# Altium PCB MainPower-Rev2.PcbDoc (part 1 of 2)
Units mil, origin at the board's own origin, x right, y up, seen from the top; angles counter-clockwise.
Board outline 7780 x 7780 mil, 4 copper layers (Top Layer, Internal Plane 1, Internal Plane 2, Bottom Layer); 128 components, 89 nets, 523 pads, 30 vias.
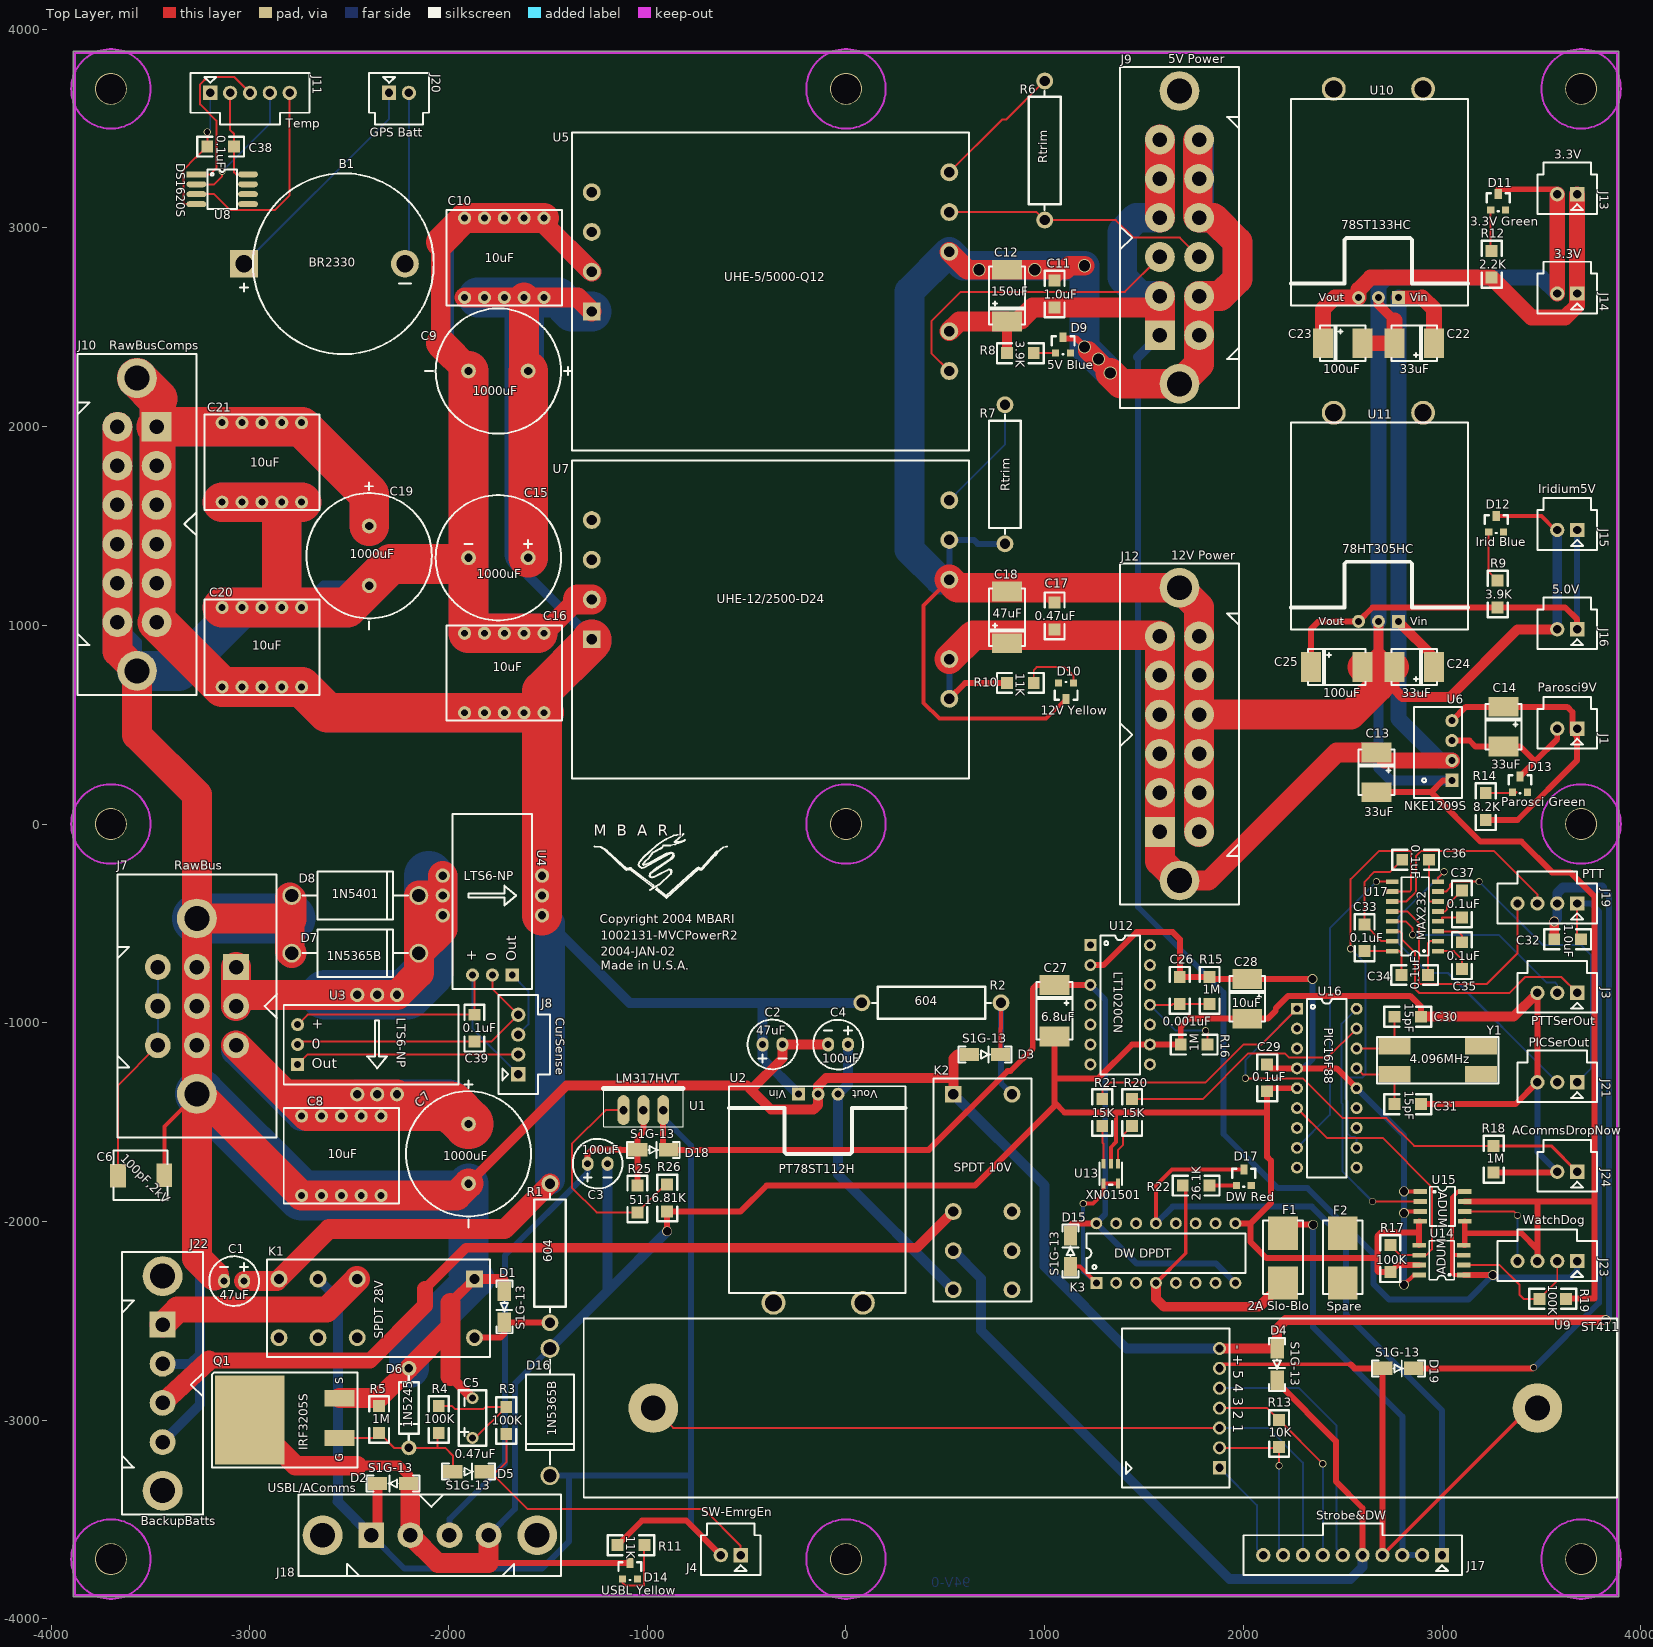
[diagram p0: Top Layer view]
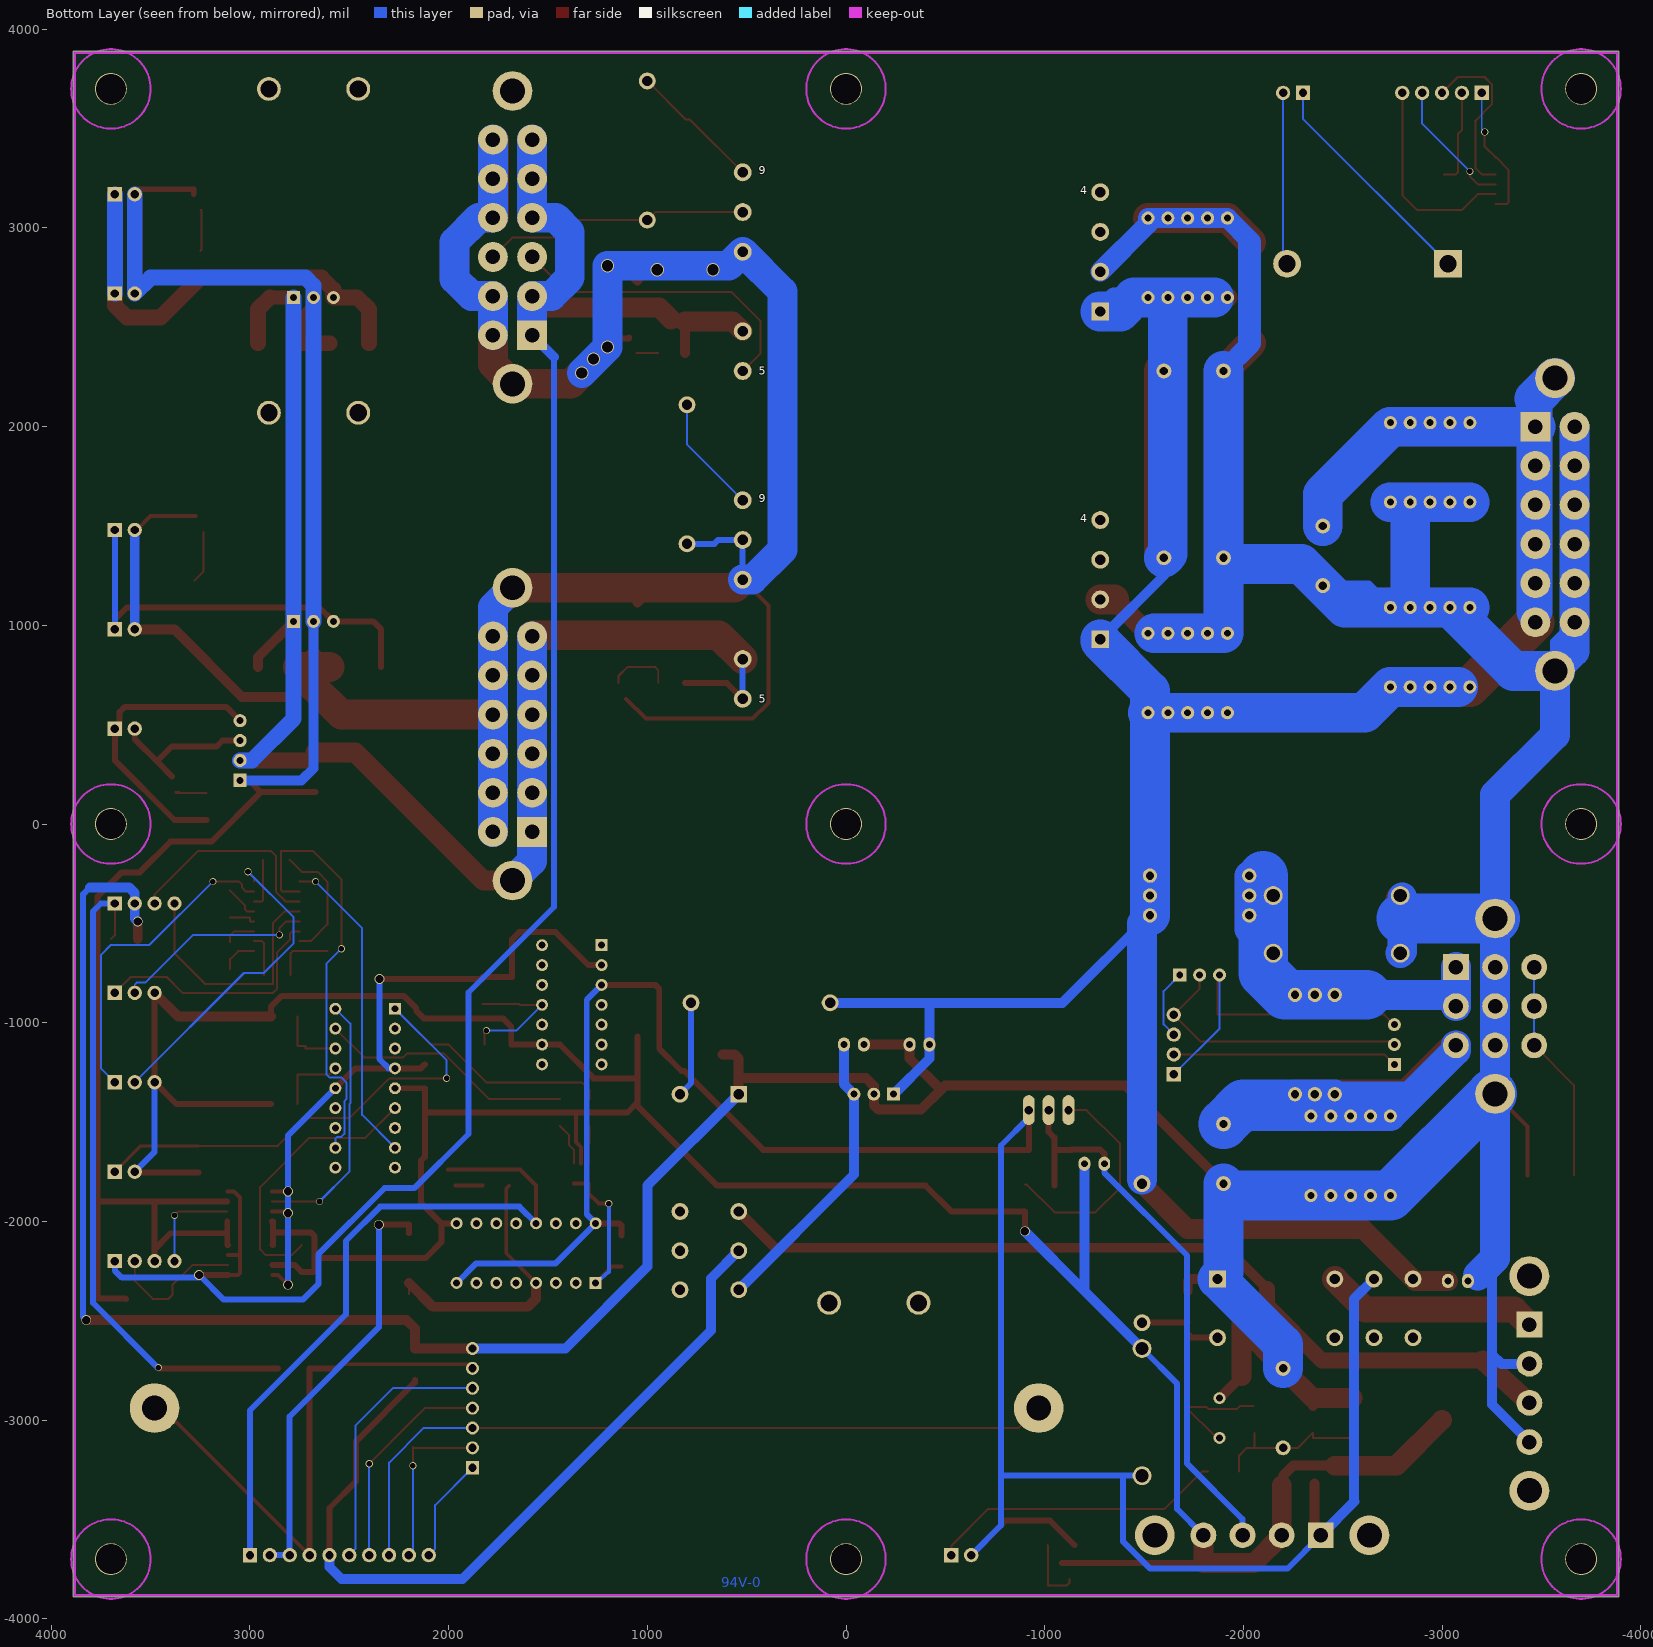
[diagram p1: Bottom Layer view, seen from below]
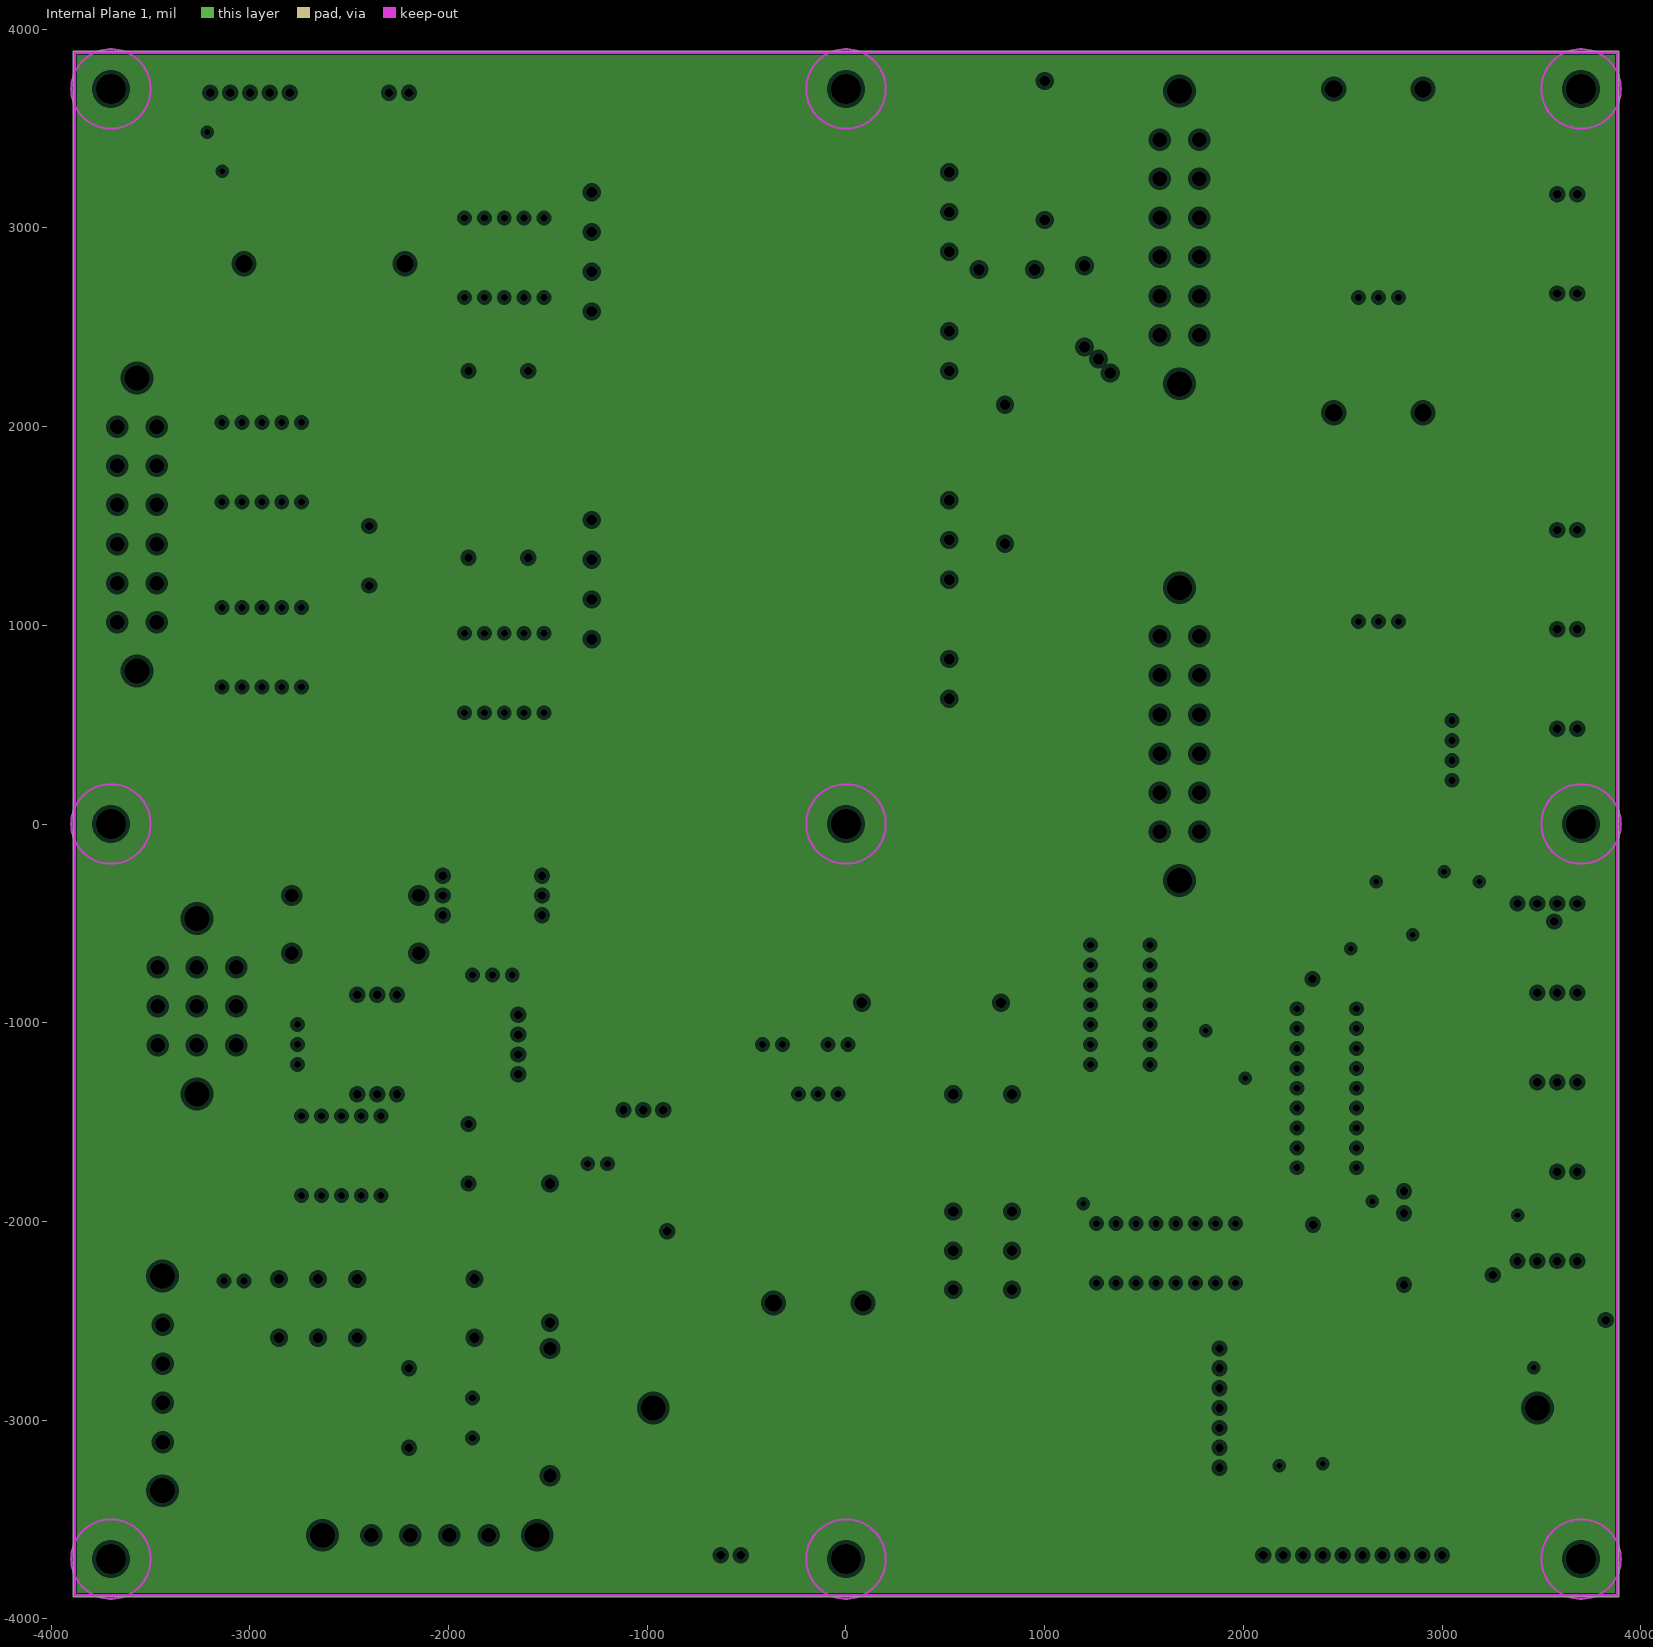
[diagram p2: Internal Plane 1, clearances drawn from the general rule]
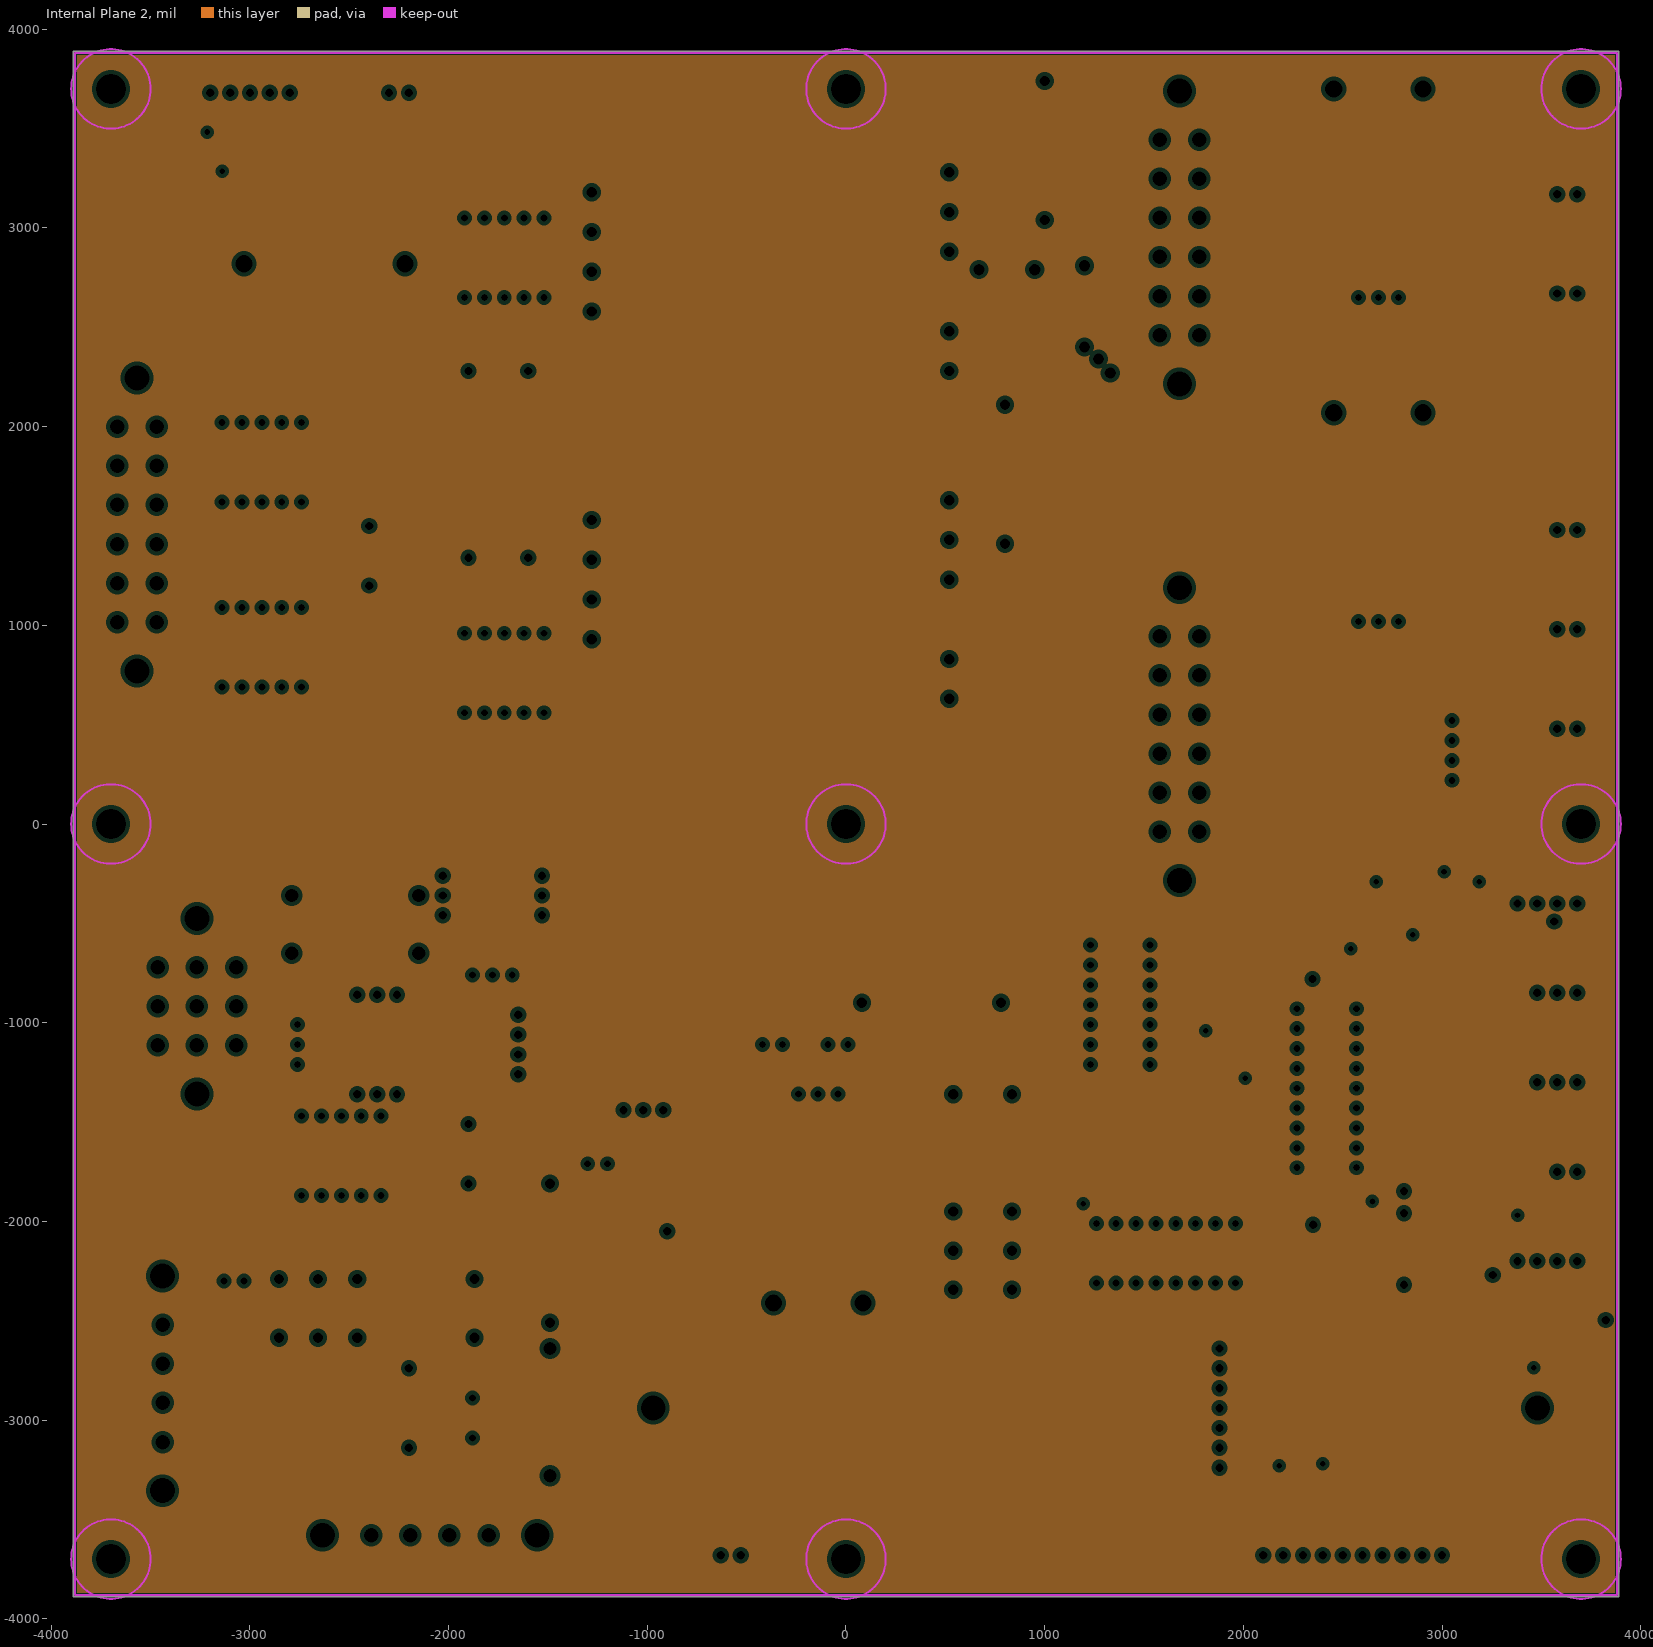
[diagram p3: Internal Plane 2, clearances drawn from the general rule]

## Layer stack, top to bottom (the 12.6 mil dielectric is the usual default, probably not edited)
Top Layer: signal copper 1.4
Dielectric: dielectric 12.6, FR-4, Dk 4.8
Internal Plane 1: plane copper 1.4
Dielectric: dielectric 12.6, FR-4, Dk 4.8
Internal Plane 2: plane copper 1.4
Dielectric: dielectric 12.6, FR-4, Dk 4.8
Bottom Layer: signal copper 1.4

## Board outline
-3890,3890 3890,3890 3890,-3890 -3890,-3890

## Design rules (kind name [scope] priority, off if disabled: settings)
Clearance Clearance_u13 [InPadClass('fineSMT')] p1: gap=10
Clearance powers [(InNetClass('BackupBattPower') OR InNetClass('RawPower') OR InNetClass('RegVoltage'))] p2: gap=20
Clearance [All] p3: gap=10
ComponentClearance [All] p1 off: gap=10 collisioncheckmode=0
FanoutControl Fanout_Small [(CompPinCount < 5)] p1: bgadir=Out bgaviamode=Centered fanoutstyle=Auto fanoutdirection=OutThenIn viagrid=1 // Fanout_Small (Default Rule)
FanoutControl Fanout_Default [All] p2: bgadir=Out bgaviamode=Centered fanoutstyle=Auto fanoutdirection=Alternating viagrid=1 // Fanout_Default (Default Rule)
FanoutControl Fanout_BGA [IsBGA] p4: bgadir=Out bgaviamode=Centered fanoutstyle=Auto fanoutdirection=Alternating viagrid=1 // Fanout_BGA (Default Rule)
FanoutControl Fanout_LCC [IsLCC] p5: bgadir=Out bgaviamode=Centered fanoutstyle=Auto fanoutdirection=Alternating viagrid=1 // Fanout_LCC (Default Rule)
HoleSize [All] p1: absolutevalues=TRUE maxlimit=250 minlimit=1 maxpercent=80.000 minpercent=20.000
PlaneClearance [All] p1: clearance=20
PlaneConnect [All] p1: planeconnectstyle=Relief reliefexpansion=20 reliefentries=4 reliefconductorwidth=10 reliefairgap=10
PolygonConnect [All] p1: connectstyle=Relief reliefconductorwidth=30 reliefentries=4 polygonreliefangle="90 Angle"
RoutingCorners [All] p1: cornerstyle=Round minsetback=50 maxsetback=1000
RoutingLayers [All] p1: top layer=Horizontal bottom layer=Vertical
RoutingPriority raw_powers [InNetClass('RawPower')] p1: routingpriority=90
RoutingPriority regpow [InNetClass('RegVoltage')] p2: routingpriority=70
RoutingPriority battpow [InNetClass('BackupBattPower')] p3: routingpriority=80
RoutingPriority [All] p4: routingpriority=0
RoutingVias RoutingVias_power [(InNetClass('BackupBattPower') OR InNetClass('RawPower') OR InNetClass('RegVoltage'))] p1: holewidth=42 width=50 viastyle="Through Hole" minholewidth=35 minwidth=43 maxholewidth=86 maxwidth=100
RoutingVias [All] p2: holewidth=28 width=36 viastyle="Through Hole" minholewidth=28 minwidth=35 maxholewidth=86 maxwidth=100
SolderMaskExpansion [All] p1: expansion=4
TestPointUsage [All] p1: valid=0 allowmultiple=FALSE
Testpoint [All] p1: side=15 testpointundercomponent=TRUE minsize=40 maxsize=100 preferedsize=60 minholesize=0 maxholesize=40 preferedholesize=32 testpointgrid=1 style=1023 order=-539222988
Width raw_power [InNetClass('RawPower')] p1: maxlimit=500 minlimit=10 preferedwidth=10 toplayer_minwidth=20 toplayer_prefwidth=250 bottomlayer_minwidth=20 bottomlayer_prefwidth=250 minimp=50.000000 maximp=50.000000 favimp=50.000000
Width backup_batt_pow [InNetClass('BackupBattPower')] p2: maxlimit=500 minlimit=10 preferedwidth=10 toplayer_minwidth=20 toplayer_prefwidth=50 bottomlayer_minwidth=20 bottomlayer_prefwidth=50 minimp=50.000000 maximp=50.000000 favimp=50.000000
Width reg_pow [InNetClass('RegVoltage')] p3: maxlimit=250 minlimit=10 preferedwidth=10 toplayer_minwidth=20 toplayer_prefwidth=80 bottomlayer_minwidth=20 bottomlayer_prefwidth=150 minimp=50.000000 maximp=50.000000 favimp=50.000000
Width [All] p4: maxlimit=500 minlimit=8 preferedwidth=12 toplayer_prefwidth=10 bottomlayer_prefwidth=10 minimp=50.000000 maximp=50.000000 favimp=50.000000
7 further rules are at their usual default settings.

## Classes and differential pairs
component class Watchdog-Rev2: C26 C27 C28 C29 C30 C31 C33 C34 C35 C36 C37 D15 D17 F1 F2 J3 J21 J25 J26 K3 R15 R16 R17 R18 R19 R20 R21 R22 R23 R24 U12 U13 U14 U15 U16 U17 Y1
component class "Parosci Iso": C13 C14 U6
component class MainPower-Rev2: B1 C19 C20 C21 C32 C38 D9 D10 D11 D12 D13 D14 D19 J1 J7 J8 J9 J10 J11 J12 J13 J14 J15 J16 J17 J18 J19 J20 J22 J23 J24 R8 R9 R10 R11 R12 R13 R14 U8 U9
component class Iridium: C24 C25 U11
component class Input-Caps-Diodes-CurrentSensing: C6 C7 C8 C39 D7 D8 U3 U4
component class ISO12V-30W-MVC-Rev2: C15 C16 C17 C18 R7 U7
component class ISO5V-25W-MVC-Rev2: C9 C10 C11 C12 R6 U5
component class GPS: C22 C23 U10
component class BattBacked-Rev2: C1 C2 C3 C4 C5 D1 D2 D3 D4 D5 D6 D16 D18 J4 K1 K2 Q1 R1 R2 R3 R4 R5 R25 R26 U1 U2
net class BackupBattPower: 12VSWBU BACKUP10+ BACKUP28+ DW28V DW+ DW- DWGND SW10VDC V+USBL
net class RegVoltage: DW5V IRID5V+ MVC3.3V+ MVC5V+ MVC12V+ MVCGND PARO9V+ PARO9VGND SW10VDC V+USBL
net class RawPower: ELEC+ LOCO+ RAWBUS+ RAWBUS-
pad class fineSMT: U13-1 U13-2 U13-3 U13-4 U13-5 U14-1 U14-2 U14-3 U14-4 U14-5 U14-6 U14-7 U14-8 U15-1 U15-2 U15-3 U15-4 U15-5 U15-6 U15-7 U15-8 U16-4 U16-5

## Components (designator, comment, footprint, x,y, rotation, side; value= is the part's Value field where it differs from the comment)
B1 "BR2330" BR2330-BAT -2530,2820 r180 top
C1 "47uF" RAD0.1L_0.25D -3030,-2300 r180 top
C2 "47uF" RAD0.1L_0.25D -420,-1110 r0 top
C3 "100uF" RAD0.1L_0.25D -1300,-1710 r0 top
C4 "100uF" RAD0.1L_0.25D 10,-1110 r180 top
C5 "0.47uF" RAD0.2_POL -1880,-3090 r90 top
C6 "100pF,2kV" ECK -3670,-1750 r0 top
C7 "1000uF" RAD0.3L_0.63D -1900,-1510 r270 top
C8 "10uF" CAPSTICK-CS4-5 -2740,-1470 r0 top
C9 "1000uF" RAD0.3L_0.63D -1600,2280 r180 top
C10 "10uF" CAPSTICK-CS4-5 -1520,2650 r180 top
C11 "1.0uF" 1206 1050,2600 r90 top
C12 "150uF" 7343pol 810,2530 r90 top
C13 "33uF" 6032pol 2670,360 r270 top
C14 "33uF" 6032pol 3310,590 r270 top
C15 "1000uF" RAD0.3L_0.63D -1600,1340 r180 top
C16 "10uF" CAPSTICK-CS4-5 -1520,560 r180 top
C17 "0.47uF" 1206 1050,980 r90 top
C18 "47uF" 7343pol 810,910 r90 top
C19 "1000uF" RAD0.3L_0.63D -2400,1500 r270 top
C20 "10uF" CAPSTICK-CS4-5 -2740,690 r180 top
C21 "10uF" CAPSTICK-CS4-5 -3140,2020 r0 top
C22 "33uF" 6032pol 2960,2420 r180 top
C23 "100uF" 6032pol 2400,2420 r0 top
C24 "33uF" 6032pol 2960,790 r180 top
C25 "100uF" 7343pol 2340,790 r0 top
C26 "0.001uF" 1206 1680,-770 r270 top
C27 "6.8uF" 7343pol 1050,-810 r270 top
C28 "10uF" 6032pol 2020,-780 r270 top
C29 "0.1uF" 1206 2120,-1210 r270 top
C30 "15pF" 1206 2760,-970 r0 top
C31 "15pF" 1206 2760,-1410 r0 top
C32 "1.0uF" 1206 3700,-580 r180 top
C33 "0.1uF" 1206 2610,-640 r90 top
C34 "0.1uF" 1206 2930,-760 r180 top
C35 "0.1uF" 1206 3100,-730 r90 top
C36 "0.1uF" 1206 2800,-180 r0 top
C37 "0.1uF" 1206 3100,-470 r90 top
C38 "0.1uF" 1206 -3080,3410 r180 top
C39 "0.1uF" 1206 -1870,-960 r270 top
D1 "S1G-13" SMA -1720,-2430 r270 top
D2 "S1G-13" SMA -2280,-3320 r180 top
D3 "S1G-13" SMA 700,-1160 r0 top
D4 "S1G-13" SMA 2170,-2720 r270 top
D5 "S1G-13" SMA -1900,-3260 r0 top
D6 "1N5245" DIODE0.4 -2200,-2740 r270 top
D7 "1N5365B" DO-201AD -2790,-650 r0 top
D8 "1N5401" DO-201AD -2790,-360 r0 top
D9 "5V Blue" SOT-23 1130,2370 r0 top
D10 "12V Yellow" SOT-23 1070,710 r180 top
D11 "3.3V Green" SOT-23 3320,3090 r0 top
D12 "Irid Blue" SOT-23 3310,1470 r0 top
D13 "Parosci Green" SOT-23 3430,160 r0 top
D14 "USBL Yellow" SOT-23 -1050,-3800 r0 top
D15 "S1G-13" SMA 1130,-2150 r90 top
D16 "1N5365B" DO-201AD -1490,-2640 r270 top
D17 "DW Red" SOT-23 2040,-1820 r0 top
D18 "S1G-13" SMA -970,-1640 r0 top
D19 "S1G-13" SMA 2780,-2740 r0 top
F1 "2A Slo-Blo" SMF-OMNIBLOK 2200,-2310 r90 top
F2 "Spare 2A Slo-Blo" SMF-OMNIBLOK 2500,-2310 r90 top
J1 "Parosci9V" CGRID2 3680,480 r0 top
J3 "PTTSerOut" CGRID3 3680,-850 r0 top
J4 "SW-EmrgEn" CGRID2 -530,-3680 r0 top
J7 "RawBus" PLC09 -3070,-720 r270 top
J8 "CurSense" CGRID4 -1650,-1260 r270 top
J9 "5V Power" PLB12 1580,2460 r90 top
J10 "RawBusComps" PLB12 -3470,2000 r270 top
J11 "Temp" CGRID5 -3200,3680 r180 top
J12 "12V Power" PLB12 1580,-40 r90 top
J13 "3.3V" CGRID2 3680,3170 r0 top
J14 "3.3V" CGRID2 3680,2670 r0 top
J15 "Iridium5V" CGRID2 3680,1480 r0 top
J16 "5.0V" CGRID2 3680,980 r0 top
J17 "Strobe&DW" CGRID10 3000,-3680 r0 top
J18 "USBL/AComms" PLA04 -2390,-3580 r0 top
J19 "PTT" CGRID4 3680,-400 r0 top
J20 "GPS Batt" CGRID2 -2300,3680 r180 top
J21 "PICSerOut" CGRID3 3680,-1300 r0 top
J22 "BackupBatts" PLA04 -3440,-2520 r270 top
J23 "WatchDog" CGRID4 3680,-2200 r0 top
J24 "ACommsDropNow" CGRID2 3680,-1750 r0 top
K1 "SPDT 28V" NAIS-LZ -1870,-2290 r180 top
K2 "SPDT 10V" NAIS-LZ 540,-1360 r270 top
K3 "DW DPDT" DIP16 1260,-2310 r90 top
Q1 "IRF3205S" D2PAK -2550,-3090 r90 top
R1 "604" AXIAL0.7 -1490,-2510 r90 top
R2 "604" AXIAL0.7 780,-900 r180 top
R3 "100K" 1206 -1710,-3070 r90 top
R4 "100K" 1206 -2050,-2930 r270 top
R5 "1M" 1206 -2350,-2930 r270 top
R6 "Rtrim" AXIAL0.7 1000,3740 r270 top
R7 "Rtrim" AXIAL0.7 800,2110 r270 top
R8 "3.9K" 1206 810,2370 r0 top
R9 "3.9K" 1206 3280,1090 r90 top
R10 "11K" 1206 810,710 r0 top
R11 "11K" 1206 -1150,-3630 r0 top
R12 "2.2K" 1206 3250,2750 r90 top
R13 "10K" 1206 2180,-3000 r270 top
R14 "8.2K" 1206 3220,20 r90 top
R15 "1M" 1206 1830,-770 r270 top
R16 "1M" 1206 1820,-1110 r180 top
R17 "100K" 1206 2740,-2120 r270 top
R18 "1M" 1206 3260,-1620 r270 top
R19 "100K" 1206 3490,-2390 r0 top
R20 "15K" 1206 1440,-1520 r90 top
R21 "15K" 1206 1290,-1520 r90 top
R22 "26.1K" 1206 1830,-1820 r180 top
R25 "511" 1206 -1050,-1820 r270 top
R26 "6.81K" 1206 -900,-1950 r90 top
U1 "LM317HVT" TO-220 -1120,-1440 r0 top
U2 "PT78ST112H" PT78ST-HORIZ -140,-1360 r180 top
U3 "LTS6-NP" LTS6-NP -2830,-910 r0 top
U4 "LTS6-NP" LTS6-NP -1980,-830 r90 top
U5 "UHE-5/5000-Q12" DATEL-UHE -1280,2580 r0 top locked
U6 "NKE1209S" NKEDCDC 3050,220 r180 top
U7 "UHE-12/2500-D24" DATEL-UHE -1280,930 r0 top locked
U8 "DS1620S" SOIC-8 -3270,3270 r0 top
U9 "ST411" ST411 3880,-2940 r270 top locked
U10 "78ST133HC" PT78ST-HORIZ 2680,2650 r0 top
U11 "78HT305HC" PT78ST-HORIZ 2680,1020 r0 top
U12 "LT1020CN" DIP14 1230,-610 r0 top
U13 "XN01501" SC-74A 1370,-1810 r0 top
U14 "ADUM1100AR" SO-G8/D5 3110,-2270 r90 top
U15 "ADUM1100AR" SO-G8/D5 2890,-1850 r270 top
U16 "PIC16F88" DIP18 2270,-930 r0 top
U17 "MAX232" SOIC-16-0.15W 2980,-640 r90 top
Y1 "4.096MHz" MA-506 2760,-1260 r0 top

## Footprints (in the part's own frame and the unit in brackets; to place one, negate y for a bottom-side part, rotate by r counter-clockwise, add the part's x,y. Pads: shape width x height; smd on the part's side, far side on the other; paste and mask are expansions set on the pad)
1206 [mil]
  rect 60x60 smd: 1(0,0) 2(135,0)
  silkscreen extent -50,-50 185,50
6032pol [mil]
  rect 100x150 smd: 1(0,0) 2(200,0)
  silkscreen extent -15,-90 215,90
7343pol [mil]
  rect 100x150 smd: 1(0,0) 2(260,0)
  silkscreen extent -15,-90 275,90
AXIAL0.7 [mil]
  round 85 hole 52: 1(0,0) 2(700,0)
  silkscreen extent 50,-80 650,80
BR2330-BAT [mil] "BR2330 lithium battery horiz mounted"
  rect 140x140 hole 86: 1(500,0)
  round 140 hole 86: 2(-310,0)
  silkscreen extent -455,-455 520,455
CAPSTICK-CS4-5 [mil]
  round 66 hole 35: 1(0,0) 1(100,0) 1(200,0) 1(300,0) 1(400,0) 2(0,-400) 2(100,-400) 2(200,-400) 2(300,-400) 2(400,-400)
  silkscreen extent -90,-440 490,40
CGRID2 [mil]
  rect 72x72 hole 42: 1(0,0)
  round 72 hole 42: 2(-100,0)
  silkscreen extent -200,-100 100,160
CGRID3 [mil]
  rect 72x72 hole 42: 1(0,0)
  round 72 hole 42: 2(-100,0) 3(-200,0)
  silkscreen extent -300,-100 100,160
CGRID4 [mil]
  rect 72x72 hole 42: 1(0,0)
  round 72 hole 42: 2(-100,0) 3(-200,0) 4(-300,0)
  silkscreen extent -400,-100 100,160
CGRID5 [mil]
  rect 72x72 hole 42: 1(0,0)
  round 72 hole 42: 2(-100,0) 3(-200,0) 4(-300,0) 5(-400,0)
  silkscreen extent -500,-100 100,160
CGRID10 [mil] "10 pin Molex CGRID-SL straight"
  rect 72x72 hole 42: 1(0,0)
  round 72 hole 42: 2(-100,0) 3(-200,0) 4(-300,0) 5(-400,0) 6(-500,0) 7(-600,0) 8(-700,0) 9(-800,0) 10(-900,0)
  silkscreen extent -1000,-100 100,160
D2PAK [mil] "IRF D2Pak SMD-220"
  rect 82x150 smd: 1(0,0) 3(200,0)
  rect 450x350 smd: 2(90,450)
  silkscreen extent -150,-90 330,640
DATEL-UHE [mil] "Datel UHE 1.6x2.0 DC/DC Converter"
  rect 90x90 hole 52: 1(0,0)
  round 90 hole 52: 2(0,200) 3(0,400) 4(0,600) 5(1800,-300) 6(1800,-100) 7(1800,300) 8(1800,500) 9(1800,700)
  silkscreen extent -100,-700 1900,900
DIODE0.4 [mil]
  round 75 hole 42: 1(0,0) 2(400,0)
  silkscreen extent 40,-50 360,50
DIP14 [mil]
  rect 60x60 hole 35: 1(0,0)
  round 60 hole 35: 2(0,-100) 3(0,-200) 4(0,-300) 5(0,-400) 6(0,-500) 7(0,-600) 8(300,-600) 9(300,-500) 10(300,-400) 11(300,-300) 12(300,-200) 13(300,-100) 14(300,0)
  silkscreen extent 50,-650 250,50
DIP16 [mil]
  rect 60x60 hole 35: 1(0,0)
  round 60 hole 35: 2(0,-100) 3(0,-200) 4(0,-300) 5(0,-400) 6(0,-500) 7(0,-600) 8(0,-700) 9(300,-700) 10(300,-600) 11(300,-500) 12(300,-400) 13(300,-300) 14(300,-200) 15(300,-100) 16(300,0)
  silkscreen extent 50,-750 250,50
DIP18 [mil]
  rect 60x60 hole 35: 1(0,0)
  round 60 hole 35: 2(0,-100) 3(0,-200) 4(0,-300) 5(0,-400) 6(0,-500) 7(0,-600) 8(0,-700) 9(0,-800) 10(300,-800) 11(300,-700) 12(300,-600) 13(300,-500) 14(300,-400) 15(300,-300) 16(300,-200) 17(300,-100) 18(300,0)
  silkscreen extent 50,-850 250,50
DO-201AD [mil]
  round 95 hole 67: 1(0,0) 2(640,0)
  silkscreen extent 55,-120 585,120
ECK [mm]
  rect 2x3 smd: 1(0.15,-0.5) 2(6.075,-0.475)
  silkscreen extent -0.4,-3.6 6.5,2.7
LTS6-NP [mil]
  round 72 hole 42: 1(370,-450) 2(470,-450) 3(570,-450) 4(570,50) 5(470,50) 6(370,50)
  rect 66x66 hole 35: a(70,-300)
  round 66 hole 35: b(70,-200) c(70,-100)
  silkscreen extent 0,-400 880,0
MA-506 [mm] "Epson Quartz Crystal"
  rect 4.1x2.1 smd: 1(0,0) 2(11.1,0) 3(11.1,3.6) 4(0,3.6)
  silkscreen extent -2.2,-1.2 13.3,4.8
NAIS-LZ [mil] "NAIS LZ Relay"
  rect 85x85 hole 52: 1(0,0)
  round 85 hole 52: 2(590.55,0) 3(787.4,0) 4(984.25,0) 5(984.25,295.28) 6(787.4,295.28) 7(590.55,295.28) 8(0,295.28)
  silkscreen extent -79,-98 1043,394
NKEDCDC [mil]
  rect 66x66 hole 35: 1(0,0)
  round 66 hole 35: 2(0,-100) 3(0,-200) 4(0,-300)
  silkscreen extent -50,-370 190,90
PLA04 [mil] "Positronic 1x4 pin"
  round 200 hole 125: 0(-244.5,0) 0(835.5,0)
  rect 130x130 hole 73: 1(0,0)
  round 130 hole 73: 2(197,0) 3(394,0) 4(591,0)
  silkscreen extent -366,-204 956,204
PLB12 [mil] "Positronic 2x6 pin"
  round 200 hole 125: 0(-244.5,-98.5) 0(1229.5,-98.5)
  rect 150x150 hole 73: 1(0,0)
  round 150 hole 73: 2(197,0) 3(394,0) 4(591,0) 5(788,0) 6(985,0) 7(0,-197) 8(197,-197) 9(394,-197) 10(591,-197) 11(788,-197) 12(985,-197)
  silkscreen extent -366,-398 1350,202
PLC09 [mil] "Positronic 3x3 pins"
  round 200 hole 125: 0(-244.5,-197) 0(638.5,-197)
  rect 130x130 hole 73: 1(0,0)
  round 130 hole 73: 2(197,0) 3(394,0) 4(0,-197) 5(197,-197) 6(394,-197) 7(0,-394) 8(197,-394) 9(394,-394)
  silkscreen extent -465,-598 859,205
PT78ST-HORIZ [mil]
  round 120 hole 86: 0(-225,1050) 0(225,1050)
  rect 65x65 hole 35: 1(100,0)
  round 65 hole 35: 2(0,0) 3(-100,0)
  silkscreen extent -440,-40 450,1000
RAD0.1L_0.25D [mil]
  oval 60x72 hole 35: 1(0,0) 2(100,0)
  silkscreen extent -75,-125 175,125
RAD0.2_POL [mil] "Polarized Cap"
  round 60 hole 35: 1(0,0) 2(200,0)
  silkscreen extent -40,-70 240,70
RAD0.3L_0.63D [mil]
  round 75 hole 42: 1(0,0) 2(300,0)
  silkscreen extent -220,-315 520,315
SC-74A [mil] "Mini5 - G1 Panasonic"
  rect 20x50 smd: 1(0,0) 2(-75,0) 3(-75,100) 4(-37,100) 5(0,100)
  silkscreen extent -95,-8 19,106
SMA [mm] "SMA Diode"
  rect 2.5x1.7 smd: 1(-2,0) 2(2,0)
  silkscreen extent -3.38,-1.02 3.38,1.02
SMF-OMNIBLOK [mil] "SMD Nano Fuse Holder"
  rect 167x150 smd: 1(0,0) 2(250,0)
  silkscreen extent -55,-100 315,100
SO-G8/D5 [mm]
  rect 0.6x1.7 smd: 1(0,0) 2(1.27,0) 3(2.54,0) 4(3.81,0) 5(3.81,5.7) 6(2.54,5.7) 7(1.27,5.7) 8(0,5.7)
  silkscreen extent -0.59,1.25 4.41,4.45
SOIC-8 [mil]
  rect 100x30 smd: 1(0,0)
  oval 100x30 smd: 2(0,-50) 3(0,-100) 4(0,-150) 5(260,-150) 6(260,-100) 7(260,-50) 8(260,0)
  silkscreen extent 55,-175 205,25
SOIC-16-0.15W [mm] "SOIC-16 0.15\"Wide 1.27mm Pitch"
  rect 0.6x1.55 smd: 1(0,0) 2(1.27,0) 3(2.54,0) 4(3.81,0) 5(5.08,0) 6(6.35,0) 7(7.62,0) 8(8.89,0) 9(8.89,5.85) 10(7.62,5.85) 11(6.35,5.85) 12(5.08,5.85) 13(3.81,5.85) 14(2.54,5.85) 15(1.27,5.85) 16(0,5.85)
  silkscreen extent -0.55,1.18 9.44,4.67
SOT-23 [mil]
  rect 36x36 smd: 1(0,0) 2(-75,0)
  rect 36x50 smd: 3(-37,80)
  silkscreen extent -95,-5 20,85
ST411 [mil]
  round 250 hole 125: 00(0,-400) 0(0,-4850)
  rect 66x66 hole 42: 1(300,-2000)
  round 66 hole 42: 2(200,-2000) 3(100,-2000) 4(0,-2000) 5(-100,-2000) 6(-200,-2000) 7(-300,-2000)
  silkscreen extent -450,-5200 450,0
TO-220 [mil]
  oval 60x150 hole 42: 1(0,0) 2(100,0) 3(200,0)
  silkscreen extent -100,-85 300,108

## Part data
B1: library part Battery, "Multicell Battery"
C1 C2 C3 C4 C5 C7 C9 C13 C14 C15 C19 C22 C23 C24 C25 C27 C28: library part "CAPACITOR POL", "Capacitor"
C6 C8 C10 C11 C16 C17 C20 C21 C26 C29 C30 C31 C32 C33 C34 C35 C36 C37 C38 C39: library part CAPACITOR, "Capacitor"
C12 C18: library part "CAPACITOR POL", "Tantalum Capacitor"
D1 D2 D3 D4 D5 D8 D15 D18 D19: library part DIODE_S, "Diode"
D6 D7 D16: library part ZENER3, "Zener Diode"
D9 D10 D11 D12 D13 D14 D17: library part LED, "LED"
F1 F2: library part "Fuse 2", "Fuse"
J1 J4 J19 J20: library part CON2, "Connector"
J3 J21: library part CON3, "Connector"
J7: library part CON3X3-PLC, "Positronic 9 pin connector"
J8: library part CON4, "Connector"
J9 J10 J12: library part CON12-PLB-2, "Positronic 12 pin connector"
J11: library part CON5, "Connector"
J13 J14 J15 J16 J24: library part CON2, "Connector C-Grid"
J17: library part CON10, "Connector"
J18 J22: library part CON4-PLA, "Positronic 4 pin connector"
J23: library part CON4, "Connector C-Grid"
K1 K2: library part RELAY-NAIS-LZ-SPDT, "Nais LZ Relay SPDT"
K3: library part RELAY-PB-V23105, "P&B V23105 Relay DPDT"
Q1: library part HEXFET-N, "HexFET"
R1 R2 R3 R4 R5 R6 R7 R8 R9 R10 R11 R12 R13 R14 R15 R16 R17 R18 R19 R20 R21 R22 R25 R26: library part RESISTOR, "Resistor"
U1: "Regulator"
U2 U10: library part PT78STXXX, "Power Trends Switching Reg"
U3 U4: "Current Transducer"
U5 U7: library part UHE, "Datel UHE DC->DC Isolated Converter"
U6: "DC->DC Isol Converter 12->9VDC"
U8: library part DS1620, "DallasSemi Digital Thermometer and Thermostat"
U9: "Novatech Strobe Beacon"
U11: library part PT78STXXX, "Power Trends Switching Reg 5V, 3A"
U12: library part LT1020, "Micropower Regulator"
U13: "Dual NPN Common Emitter Transistor"
U14 U15: "Digital Isolator"
U16: "PIC16F88 microcontroller DIP,SOIC package"
U17: "MAX232 Communications Chip"
Y1: library part XTAL, "Crystal Oscillator"

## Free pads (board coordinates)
  round 160 hole 152: 0(-3700,-3700) 1(-3700,0) 1(0,-3700) 1(0,0) 1(0,3700) 1(3700,-3700) 1(3700,0) 2(3700,3700) 3(-3700,3700)

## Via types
v1: diameter 36, hole 28, Top Layer to Bottom Layer, 15 vias
v2: diameter 50, hole 42, Top Layer to Bottom Layer, 9 vias
v3: diameter 66, hole 56, Top Layer to Bottom Layer, 6 vias

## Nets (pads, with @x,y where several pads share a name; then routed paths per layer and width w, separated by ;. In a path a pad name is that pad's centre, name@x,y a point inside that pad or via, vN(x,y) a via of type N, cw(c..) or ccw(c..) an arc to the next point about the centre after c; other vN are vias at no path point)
12VSWBU: C4.1 K2.4 U2.3 | length 1495.2
  Bottom Layer w50: C4.1@10,-1110 10,-1310 U2.3@-40,-1360 -40,-1764.25 K2.4@540,-2344.25
AN0V: C39.2 J8.4 U3.b U4.b | length 1426
  Top Layer w10: U3.b@-2760,-1110 -2745,-1095 C39.2@-1870,-1095 -1785,-1095 J8.4@-1650,-960 -1780,-830 U4.b@-1780,-760
AN5V: C39.1 J8.1 U3.c U4.c | length 1710.1
  Top Layer w10: U3.c@-2760,-1010 -2710,-960 C39.1@-1870,-960 -1870,-770 U4.c@-1880,-760
  Bottom Layer w10: U4.c@-1880,-760 -1880,-1030 J8.1@-1650,-1260
BACKUP10+: J22.3 K2.2 | length 6872.8
  Top Layer w30: -1838,-2123 367.55,-2123 K2.2@540,-1950.55
  Top Layer w50: -2120,-2340 -1913,-2133 357.55,-2133 K2.2@540,-1950.55
  Top Layer w80: -3207,-2701 -2396,-2701 -2120,-2425 -2120,-2340
  Top Layer w100: J22.3@-3440,-2914 -3207,-2701
BACKUP28+: J22.1 K1.2 | length 2149.4
  Top Layer w50: J22.1@-3440,-2520 -3370,-2450 -2620.55,-2450 K1.2@-2460.55,-2290
  Top Layer w130: J22.1@-3440,-2520 -3364.31,-2444.31 -2614.86,-2444.31 K1.2@-2460.55,-2290
DROPNOW: J24.1 R18.1 R21.2 U16.1 | length 3517.2
  Top Layer w10: R21.2@1290,-1385 1290,-1340 1330,-1300 1810,-1300 2000,-1110 2090,-1110 U16.1@2270,-930 ; v1(2010,-1280) 2300,-1280 2500,-1480 2520,-1480 2720,-1480 2860,-1620 R18.1@3260,-1620
  Top Layer w15: R18.1@3260,-1620 3550,-1620 J24.1@3680,-1750
  Bottom Layer w10: v1(2010,-1280) 2010,-1190 U16.1@2270,-930
DW5V: C26.1 C28.1 C29.1 R15.1 U12.2 U14.8 U15.1 U15.3 U16.4 U16.14 | length 3757.3
  Top Layer w20: v2(2809,-2319) 2858,-2270 U14.8@2885.59,-2270 ; v2(2809,-1959) 2810,-1950 U15.3@2890,-1950 ; v2(2809,-1849) 2810,-1850 U15.1@2890,-1850
  Top Layer w30: U12.2@1230,-710 1297,-710 1462.36,-544.64 1644.64,-544.64 1680,-580 C26.1@1680,-770 R15.1@1830,-770 1830,-780 C28.1@2020,-780 v2(2348,-780) ; C29.1@2120,-1210 2140,-1230 U16.4@2270,-1230 2470,-1230 U16.14@2570,-1330
  Bottom Layer w30: U16.4@2270,-1230 2302,-1230 2348,-1184 v2(2348,-780) ; U16.14@2570,-1330 2809,-1569 v2(2809,-1849) v2(2809,-1959) v2(2809,-2319)
DW28V: C27.1 D2.2 D15.2 D16.2 D18.2 J4.2 J18.1 K1.3 K3.8 K3.16 R11.1 U1.3 U12.3 | length 11972.1
  Top Layer w30: R11.1@-1150,-3630 -1026,-3506 -804,-3506 J4.2@-630,-3680 ; U1.3@-920,-1440 -920,-1640 D18.2@-891.26,-1640 417,-1640 814,-1243 828,-1243 940,-1131 940,-830 960,-810 C27.1@1050,-810 U12.3@1230,-810 ; D15.2@1130,-2071.26 1130,-2020 1140,-2010 K3.16@1260,-2010
  Top Layer w50: J18.1@-2390,-3580 -2358.74,-3548.74 D2.2@-2358.74,-3320
  Bottom Layer w30: J18.1@-2390,-3580 -2222,-3748 -1531,-3748 -1395,-3612 -1395,-3280 ; D16.2@-1490,-3280 -1395,-3280 ; U1.3@-920,-1440 -920,-1478 -780,-1618 -780,-3280 ; J4.2@-630,-3680 -780,-3530 -780,-3280 ; U12.3@1230,-810 1305,-885 1305,-1965 K3.16@1260,-2010 1463,-2213 1863,-2213 K3.8@1960,-2310 ; -1395,-3280 -780,-3280
  Bottom Layer w50: K1.3@-2657.4,-2290 -2557.44,-2389.97 -2557.44,-3411.16 ; -2559.44,-3409.16 J18.1@-2390,-3580
DW+: F1.2 J17.2 J17.3 | length 2143
  Top Layer w30: F1.2@2200,-2060 2200,-2017 v2(2351,-2017)
  Bottom Layer w30: v2(2351,-2017) 2351,-2533 2800,-2982 J17.3@2800,-3680 J17.2@2900,-3680
DW-: D17.3 J17.1 K3.13 | length 3511.2
  Top Layer w20: K3.13@1560,-2010 1560,-1820 1640,-1740 D17.3@2003,-1740
  Bottom Layer w30: K3.13@1560,-2010 1644,-1926 2345,-1926 2517,-2098 2517,-2468 3000,-2951 J17.1@3000,-3680
DWGND: C3.2 C27.2 C28.2 C29.2 C30.2 C31.2 D2.1 D14.3 D16.1 J3.3 J18.2 J18.4 J21.3 J24.2 K3.9 Q1.2 R16.2 R17.2 R18.2 R26.1 U12.9 U13.4 U14.5 U14.7 U15.4 U16.5 | length 16227.3
  Top Layer w20: U13.4@1333,-1710 1333,-1627 1360,-1600 1360,-1452
  Top Layer w30: Q1.2@-3000,-3036 Q1.2@-3000,-3000 ; -1799,-3720 D14.3@-1087,-3720 ; v2(-900,-2050) R26.1@-900,-1950 -530,-1950 -400,-1820 648,-1820 1050,-1418 1050,-1402 ; 1050,-1280 1270,-1280 1440,-1110 U12.9@1530,-1110 R16.2@1685,-1110 1685,-1020 1725,-980 C28.2@2020,-980 2123,-980 2163,-940 2163,-927 2225.15,-864.85 2839.85,-864.85 2895,-920 C30.2@2895,-970 ; C27.2@1050,-1070 1050,-1402 ; K3.9@1960,-2010 2036.75,-2010 ; U16.5@2270,-1330 2120,-1330 C29.2@2120,-1345 2120,-1452 ; U14.7@2885.59,-2220 2775,-2220 R17.2@2740,-2255 2680,-2255 2674.42,-2249.42 2674.42,-2185 ; U14.5@2885.59,-2120 2885,-2120 2885,-2055 ; U15.4@2890,-2000 2885,-2000 2885,-2055 ; C31.2@2895,-1410 3370,-1410 J21.3@3480,-1300 J3.3@3480,-850 ; R18.2@3260,-1755 3575,-1755 J24.2@3580,-1750 ; 1050,-1402 1100,-1452 2120,-1452 ; 2036.75,-2010 2138.38,-1908.37 2138.38,-1693.38 2120,-1675 2120,-1452 ; 2036.75,-2010 2036.75,-2105 2116.75,-2185 2674.42,-2185 ; 2674.42,-2185 2674.42,-2075.42 2694.84,-2055 2885,-2055
  Top Layer w50: -2460,-3230 -2250,-3230 -2201.26,-3278.74 D2.1@-2201.26,-3320 D2.1@-2193,-3328.26 ; C30.2@2895,-970 3360,-970 J3.3@3480,-850
  Top Layer w100: Q1.2@-3000,-3000 -2770,-3230 -2460,-3230 ; D2.1@-2193,-3328.26 J18.2@-2193,-3580 -2053,-3720 -1799,-3720 J18.4@-1799,-3580
  Bottom Layer w30: J18.4@-1799,-3580 -1667,-3448 -1667,-2817 D16.1@-1490,-2640 ; J21.3@3480,-1300 3480,-1650 3530,-1700 J24.2@3580,-1750
  Bottom Layer w50: D16.1@-1490,-2640 -1200,-2350 ; C3.2@-1200,-1710 -1200,-2350 ; v2(-900,-2050) -1200,-2350
ELEC+: C1.1 C2.1 C9.1 C10.1 C15.1 C16.1 C19.1 C20.1 C21.1 J10.0@-3568.5,2244.5 J10.1 J10.2 J10.3 J10.4 J10.5 J10.6 K1.4 R1.2 R2.2 U2.1 U4.1 U4.2 U4.3 U5.1 U7.1 | length 34725.2
  Top Layer w50: J10.6@-3470,1015 -3470,922 -3238,690 C20.1@-3140,690 ; C1.1@-3030,-2300 -3020,-2290 K1.4@-2854.25,-2290 -2623.25,-2059 -1739,-2059 R1.2@-1490,-1810
  Top Layer w100: C1.1@-3030,-2300 -2864.25,-2300 -2602.25,-2038 -1718,-2038 R1.2@-1490,-1810 ; C10.1@-1920,2650 -1350,2650 U5.1@-1280,2580 ; C9.1@-1620,2300 C9.1@-1600,2280
  Top Layer w150: C9.1@-1620,2300 C10.1@-1620,2650
  Top Layer w180: J10.6@-3465,1015 -3465,2141
  Top Layer w200: J10.0@-3568.5,2244.5 -3465,2141 ; J10.1@-3470,2000 -2740,2000 -2400,1660 C19.1@-2400,1500 ; J10.6@-3465,1015 C20.1@-3140,690 C20.1@-2740,690 -2610,560 C16.1@-1520,560 ; C15.1@-1600,1340 C9.1@-1600,2280 ; U4.1@-1530,-460 -1530,670 -1280,920 U7.1@-1280,930
  Bottom Layer w50: J10.0@-3568.5,2244.5 -3470,2146 J10.1@-3470,2000 ; J10.6@-3470,1015 J10.5@-3470,1212 J10.4@-3470,1409 J10.3@-3470,1606 J10.2@-3470,1803 J10.1@-3470,2000 ; -3080,690 C20.1@-3040,690 C20.1@-2940,690 C20.1@-2840,690 C20.1@-2740,690 -2610,560 C16.1@-1920,560 C16.1@-1820,560 C16.1@-1720,560 C16.1@-1620,560 C16.1@-1520,560 ; C19.1@-2400,1500 -2400,1680 C21.1@-2740,2020 C21.1@-2840,2020 C21.1@-2940,2020 C21.1@-3040,2020 C21.1@-3140,2020 -3305,2020 -3325,2000 J10.1@-3470,2000 ; C10.1@-1920,2650 C10.1@-1820,2650 C10.1@-1720,2650 C10.1@-1620,2650 ; C10.1@-1520,2650 C10.1@-1620,2650 ; R1.2@-1490,-1810 -1490,-500 U4.1@-1530,-460 ; U5.1@-1280,2580 -1550,2580 C10.1@-1620,2650 ; U2.1@-240,-1360 -420,-1180 C2.1@-420,-1110 -420,-900 ; R2.2@80,-900 -420,-900 ; C10.1@-1620,2650 -1620,2280 C9.1@-1600,2280 C15.1@-1600,1340 -1600,1250 U7.1@-1280,930 -1520,690 C16.1@-1520,560 ; U4.1@-1530,-460 U4.2@-1530,-360 U4.3@-1530,-260 -1530,254 -1520,264 C16.1@-1520,560 ; U4.1@-1530,-460 -1090,-900 -420,-900
  Bottom Layer w100: C9.1@-1620,2300 C10.1@-1620,2650 ; C15.1@-1600,1340 C9.1@-1600,2280 ; -1350,2650 U5.1@-1280,2580
  Bottom Layer w150: U4.1@-1530,-460 -1490,-500 R1.2@-1490,-1789.44
  Bottom Layer w180: J10.6@-3465,1070 -3465,2141
  Bottom Layer w200: J10.0@-3568.5,2244.5 -3465,2141 ; J10.1@-3470,2000 -2740,2000 -2400,1660 C19.1@-2400,1500 ; -3080,690 C20.1@-2740,690 -2610,560 C16.1@-1520,560 ; C10.1@-1853,2650 -1450,2650 -1380,2580 U5.1@-1280,2580 ; C10.1@-1620,2650 -1620,1360 C15.1@-1600,1340 ; U4.1@-1530,-460 -1530,670 -1280,920 U7.1@-1280,930
ELECCUR: J8.3 U4.a | length 354.7
  Bottom Layer w10: U4.a@-1680,-760 -1599,-841 -1599,-1009 J8.3@-1650,-1060
IRID5V+: C25.1 J15.1 J16.1 R9.1 U11.3 | length 2150.4
  Top Layer w30: C25.1@2340,790 2340,980 2380,1020 U11.3@2580,1020 2650,1090 R9.1@3280,1090 3620,1090 3680,1030 J16.1@3680,980
  Bottom Layer w30: J16.1@3680,980 J15.1@3680,1480
ISO5VSENSE+: J9.3 U5.5 | length 1571.5
  Top Layer w10: U5.5@520,2280 430,2370 430,2530 578,2678 619,2678 1404,2678 J9.3@1580,2854
ISO5VSENSE-: J9.9 R6.2 U5.8 | length 1350.6
  Top Layer w10: U5.8@520,3080 960,3080 R6.2@1000,3040 1358,3040 1447,2951 1680,2951 J9.9@1777,2854
LOCO+: C7.1 C8.1 J7.3 U3.1 U3.2 U3.3 | length 6630.7
  Top Layer w150: C8.1@-2340,-1470 -2714,-1470 J7.3@-3070,-1114 -2824,-1360 U3.3@-2260,-1360
  Top Layer w250: -2690,-1420 -1990,-1420 C7.1@-1900,-1510
  Bottom Layer w50: J7.3@-3070,-1114 -3070,-1140 C8.1@-2740,-1470 C8.1@-2640,-1470 C8.1@-2540,-1470 C8.1@-2440,-1470 C8.1@-2340,-1470 -2330,-1480 -1930,-1480 C7.1@-1900,-1510 ; C8.1@-2460,-1470 U3.1@-2460,-1360 U3.2@-2360,-1360 U3.3@-2260,-1360
  Bottom Layer w150: J7.3@-3070,-1114 -3070,-1140 C8.1@-2740,-1470 -1940,-1470 C7.1@-1900,-1510 ; -2840,-1370 -2470,-1370 U3.1@-2460,-1360 U3.3@-2260,-1360
  Bottom Layer w250: -2280,-1410 -2000,-1410 C7.1@-1900,-1510
LOCOCUR: J8.2 U3.a | length 1130.7
  Top Layer w10: U3.a@-2760,-1210 -2710,-1160 J8.2@-1650,-1160
MVC3.3V+: C23.1 J13.1 J14.1 R12.1 U10.3 | length 2707.4
  Top Layer w80: C23.1@2400,2420 2400,2590 2460,2650 U10.3@2580,2650 2580,2690 2640,2750 R12.1@3250,2750 3450,2550 3620,2550 3680,2610 J14.1@3680,2670 J13.1@3680,3170
  Bottom Layer w80: J14.1@3680,2670 J13.1@3680,3170
MVC5V+: C11.1 C12.1 J9.1 J9.2 J9.4 J9.5 J9.6 J23.1 R8.1 U5.6 U14.1 U14.3 U15.8 | length 10404.1
  Top Layer w20: U14.1@3110,-2270 3060,-2270 3050,-2260 3050,-2160 ; U14.3@3110,-2170 3060,-2170 3050,-2160 ; U15.8@3114.41,-1850 3080,-1850 3050,-1880 3050,-2160
  Top Layer w30: C12.1@880,2530 C12.1@880,2540 ; 1523,2600 J9.2@1580,2657 ; U14.1@3110,-2270 v2(3256,-2270)
  Top Layer w50: R8.1@810,2370 C12.1@810,2530
  Top Layer w100: U5.6@520,2480 570,2530 C12.1@810,2530 ; C12.1@880,2540 940,2600 C11.1@1050,2600 1523,2600
  Top Layer w150: J9.1@1580,2460 J9.2@1580,2657 ; J9.4@1580,3051 J9.6@1580,3445
  Bottom Layer w30: 1470,2350 1470,-418 1900,-848 1900,-1560 2173,-1833 2323,-1833 2656,-2166 2656,-2316 2734,-2394 3132,-2394 v2(3256,-2270) 3256,-2283 3645,-2283 3680,-2248 J23.1@3680,-2200
  Bottom Layer w50: 1470,2350 J9.1@1580,2460
  Bottom Layer w150: J9.1@1580,2460 J9.2@1580,2657 1483,2657 1390,2750 1390,2980 1461,3051 J9.4@1580,3051 J9.5@1580,3248 J9.6@1580,3445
